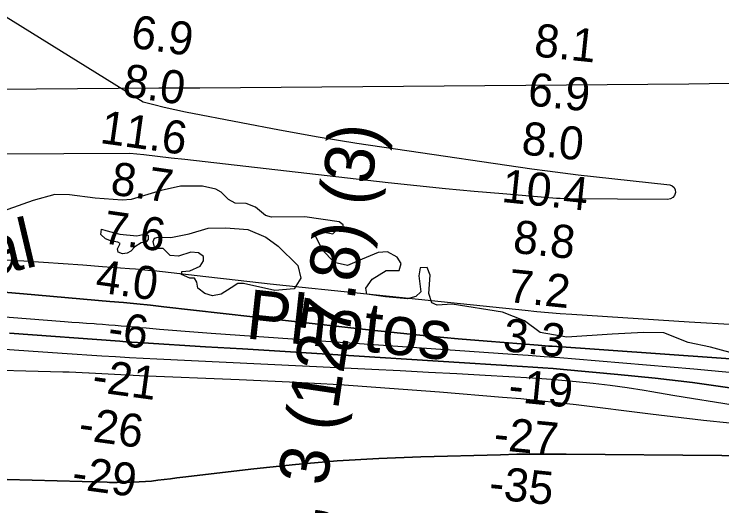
# Model space of a CAD drawing. Extents: x 3535183 to 3573198, y 534952 to 560562.
# Drawn here: x 3563273 to 3564705, y 545747 to 546742 of the extents above; entities that cross this region are included whole.
import ezdxf

# ---------------------------------------------------------------- set-up
doc = ezdxf.new("R2010")
doc.units = 0
for name, color, linetype in [('V-CHAN-NAID', 7, 'Continuous'), ('V-GRID-MAJR', 7, 'Continuous'), ('V-RIVR-EDGE', 7, 'Continuous'), ('V-RIVR-IDEN', 7, 'Continuous'), ('V-RIVR-RANG', 7, 'Continuous'), ('V-TOPO-DPTH', 7, 'Continuous'), ('V-TOPO-MINR', 7, 'Continuous'), ('V-TOPO-WATR', 7, 'Continuous')]:
    doc.layers.add(name, color=color, linetype=linetype)

msp = doc.modelspace()

# ---------------------------------------------------------------- linework, layer by layer
at = {"layer": 'V-GRID-MAJR'}
msp.add_spline([(3539332.196, 546413.546), (3544607.59, 546451.528), (3549882.9790000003, 546490.277), (3555158.363, 546529.794), (3560433.741, 546570.077), (3565709.113, 546611.128), (3570984.478, 546652.946), (3570984.4790000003, 546652.946)], degree=3, dxfattribs=at)
at = {"layer": 'V-RIVR-EDGE'}
for points in [[(3563920.6087827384, 546239.1026320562), (3563896.164998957, 546265.5103381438), (3563882.7532650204, 546293.116219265), (3563893.1907726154, 546301.6685891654), (3563917.6890995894, 546297.3189224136), (3563926.9026756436, 546306.4870458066), (3563938.555024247, 546310.7473223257), (3563938.5671449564, 546315.6491088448), (3563930.61689275, 546321.7960381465), (3563860.7906762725, 546331.7723312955), (3563793.3880814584, 546330.7135444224), (3563781.7554290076, 546334.4186709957), (3563761.5764670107, 546351.0121984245), (3563742.6002253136, 546358.4118459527), (3563720.5437010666, 546359.0791124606), (3563706.4692458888, 546366.4666392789), (3563691.801763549, 546381.82108428), (3563681.400618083, 546387.9740739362), (3563653.841704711, 546393.5567627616), (3563609.72562604, 546393.6658491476), (3563570.4901226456, 546385.1846884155), (3563509.785061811, 546366.9529827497), (3563492.011540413, 546365.1587503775), (3563436.8770476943, 546369.5841715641)], [(3563436.8770476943, 546369.5841715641), (3563385.4234401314, 546375.8386721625), (3563355.401512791, 546376.5256348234), (3563311.8693707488, 546364.9914631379), (3563187.3759363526, 546320.5702241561), (3563091.099591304, 546288.9464807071), (3563021.8209493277, 546272.5741562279), (3562912.122264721, 546264.2672306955), (3562837.9418362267, 546247.9070269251), (3562747.8321166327, 546232.1989387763), (3562660.2020769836, 546228.1265332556), (3562527.250208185, 546232.1316473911), (3562435.984736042, 546244.6118619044), (3562365.595794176, 546274.8095395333), (3562331.952070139, 546297.5636320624), (3562297.674411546, 546311.7411132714), (3562267.640363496, 546307.5262894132), (3562174.503389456, 546306.531136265), (3562088.688793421, 546293.2633357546), (3562023.721940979, 546286.0712553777)], [(3563448.336980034, 546296.0285870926), (3563449.588183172, 546306.4418532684), (3563458.77297254, 546303.9682336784)], [(3563458.77297254, 546303.9682336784), (3563486.94006396, 546296.5458598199), (3563521.24499415, 546293.3973982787), (3563539.635784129, 546297.0282855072), (3563544.529995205, 546293.9525482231), (3563544.5102990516, 546285.9871451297), (3563540.2091151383, 546281.0959642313), (3563529.7882735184, 546279.2835507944), (3563517.51259598, 546270.7357261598), (3563508.9132583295, 546262.1788109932), (3563501.54997293, 546257.9079288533), (3563492.356093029, 546256.7052085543), (3563483.7855420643, 546259.7900363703), (3563482.5782764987, 546267.1457463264), (3563487.5058195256, 546277.5499219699), (3563483.2243317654, 546280.6241441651), (3563470.361687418, 546282.4941309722), (3563458.1193418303, 546287.4262192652), (3563448.336980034, 546296.0285870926)], [(3563564.740774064, 546290.226210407), (3563589.860914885, 546289.5513684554), (3563627.2567332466, 546297.4243511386), (3563665.887088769, 546308.9706435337), (3563701.426556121, 546309.4954917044), (3563746.146267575, 546305.7085503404), (3563782.2590659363, 546290.3010772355), (3563807.3367842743, 546272.4699824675), (3563847.0668340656, 546233.1572095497), (3563853.130433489, 546207.4076794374), (3563839.5974924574, 546185.9956953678), (3563800.374109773, 546182.416321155), (3563737.2984553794, 546196.6650115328), (3563725.6567123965, 546196.693798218), (3563712.1555882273, 546188.1490037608), (3563691.9039019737, 546175.3318120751), (3563674.12583531, 546171.6994097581), (3563658.819873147, 546176.6390734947), (3563644.7529934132, 546187.0902168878), (3563642.945125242, 546199.3492284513), (3563638.063034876, 546207.3267522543), (3563628.872185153, 546207.3494785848), (3563611.7341134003, 546214.7445808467), (3563612.3619876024, 546220.8702989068), (3563628.297339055, 546222.6690765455), (3563649.765381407, 546231.8068981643), (3563655.919886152, 546242.8207669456), (3563655.9410973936, 546251.398893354), (3563646.15570542, 546258.7758145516), (3563630.22792941, 546260.0406534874), (3563605.699300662, 546252.1358539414), (3563588.546078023, 546253.4037230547), (3563574.4882888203, 546267.531206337), (3563557.9447593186, 546267.5721137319), (3563554.303266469, 546281.6738405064), (3563557.3835490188, 546288.4062215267)], [(3563557.3835490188, 546288.4062215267), (3563564.740774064, 546290.226210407)], [(3564743.648330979, 546050.7984651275), (3564681.805698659, 546068.1077419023), (3564636.486899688, 546077.410708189), (3564586.9032789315, 546096.5278531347), (3564546.466570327, 546097.8532956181), (3564482.734255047, 546094.3345249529), (3564390.809091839, 546087.8218317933), (3564336.9136815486, 546097.7587326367), (3564305.72236586, 546121.1194881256), (3564261.035986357, 546138.3863424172), (3564159.363308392, 546154.568653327), (3564128.7225973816, 546152.8062378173), (3564117.7056984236, 546157.735295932), (3564111.6239179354, 546176.1321462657), (3564114.77995492, 546213.5006930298), (3564108.6905989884, 546228.8339267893), (3564094.596447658, 546228.2560505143), (3564091.493438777, 546212.3328197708), (3564095.70220228, 546179.8478784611), (3564085.874387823, 546170.0685468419), (3564068.7075293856, 546165.8219061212), (3564023.9878179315, 546169.608847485), (3563986.6253315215, 546175.2157777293), (3563984.8174633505, 546187.4747892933), (3563997.115867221, 546205.2134636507), (3564025.9578005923, 546222.911230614), (3564051.6921798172, 546222.847596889), (3564056.016090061, 546236.9296275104), (3564048.0825038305, 546249.8165132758), (3564028.502629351, 546260.8940157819), (3564009.5051764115, 546259.7155369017), (3563976.995993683, 546245.7032003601), (3563947.5534577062, 546232.9087350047), (3563920.6087827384, 546239.1026320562)]]:
    msp.add_lwpolyline(points, dxfattribs=at)
at = {"layer": 'V-TOPO-DPTH'}
for points in [[(3562632.7349828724, 547124.667376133), (3563534.0579824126, 546564.236942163), (3563555.4448023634, 546558.7873249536), (3563576.896173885, 546553.6175180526), (3563598.4443727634, 546548.8674266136), (3563620.0571232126, 546544.3971454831), (3563732.2801317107, 546522.3255797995), (3563810.1535174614, 546507.6194501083), (3563888.161065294, 546493.6994274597), (3563966.3698562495, 546480.9585653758), (3564044.712809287, 546469.0038103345), (3564320.5354716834, 546429.0427956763), (3564351.62725476, 546424.7017036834), (3564382.746292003, 546420.5745643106), (3564413.9062104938, 546416.768353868), (3564445.0933831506, 546413.1760960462), (3564599.0478739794, 546396.246450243), (3564604.374294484, 546394.1276473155), (3564608.362350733, 546390.9867049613), (3564610.342860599, 546386.3125534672), (3564610.9850062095, 546380.616262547), (3564608.6808124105, 546374.985924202), (3564605.340105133, 546370.5786452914), (3564600.4446276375, 546368.0059555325), (3564594.5126366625, 546366.6563252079), (3564392.151822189, 546368.2597698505), (3564384.79629077, 546368.3997592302), (3564377.4456505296, 546368.6485274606), (3564370.102347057, 546369.0604639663), (3564362.7639347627, 546369.5811793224), (3564261.4945348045, 546377.8983039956), (3564203.5519701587, 546382.93338135), (3564145.645231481, 546388.3338792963), (3564087.792231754, 546394.2825081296), (3564029.975057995, 546400.5965575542), (3563618.427723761, 546447.5135071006), (3563590.6980362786, 546450.6660744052), (3563562.967061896, 546453.8072492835), (3563535.234157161, 546456.9313355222), (3563507.4999655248, 546460.0440293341), (3562438.845673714, 546454.3916878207)], [(3563212.017228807, 546182.3422016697), (3563292.346897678, 546175.9260687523), (3563466.9244357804, 546160.5519434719), (3563494.239026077, 546158.0473020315), (3563521.5404849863, 546155.4115806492), (3563548.8222468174, 546152.5792393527), (3563576.090877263, 546149.6158181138), (3563996.1826714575, 546102.4305413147), (3564054.592260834, 546096.1519105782), (3564113.0376461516, 546090.2451974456), (3564171.5367253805, 546084.8963607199), (3564230.07160055, 546079.9194415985), (3564333.1316902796, 546071.6517846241), (3564340.164161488, 546071.0981699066), (3564347.197683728, 546070.5585268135), (3564354.2327825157, 546070.0398411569), (3564361.2689323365, 546069.5351271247), (3565026.056004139, 546022.8442086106)], [(3563212.017228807, 546182.3422016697), (3563292.346897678, 546175.9260687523), (3563466.9244357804, 546160.5519434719), (3563494.239026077, 546158.0473020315), (3563521.5404849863, 546155.4115806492), (3563548.8222468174, 546152.5792393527), (3563576.090877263, 546149.6158181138), (3563996.1826714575, 546102.4305413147), (3564054.592260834, 546096.1519105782), (3564113.0376461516, 546090.2451974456), (3564171.5367253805, 546084.8963607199), (3564230.07160055, 546079.9194415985), (3564333.1316902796, 546071.6517846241), (3564340.164161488, 546071.0981699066), (3564347.197683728, 546070.5585268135), (3564354.2327825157, 546070.0398411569), (3564361.2689323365, 546069.5351271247), (3565026.056004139, 546022.8442086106)], [(3563264.096077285, 546096.1309951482), (3563487.180566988, 546079.7043587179), (3563498.9790974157, 546078.8574095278), (3563510.7795814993, 546078.0394163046), (3563522.582996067, 546077.2648570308), (3563534.38836429, 546076.5192537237), (3563660.5084267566, 546068.7867398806), (3563735.374514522, 546064.184039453), (3563810.239566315, 546059.5645952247), (3563885.103064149, 546054.920035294), (3563959.965526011, 546050.258731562), (3564301.2877432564, 546028.9488612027), (3564321.9931521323, 546027.5684165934), (3564342.689647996, 546026.0715641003), (3564363.3727743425, 546024.400099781), (3564384.046987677, 546022.6122275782), (3564494.088390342, 546012.6280233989), (3564569.673329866, 546004.9479271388), (3564645.12069832, 545996.1852597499), (3564720.3617101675, 545985.7987356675)], [(3564720.3617101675, 545985.7987356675), (3564645.12069832, 545996.1852597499), (3564569.673329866, 546004.9479271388), (3564494.088390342, 546012.6280233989), (3564384.046987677, 546022.6122275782), (3564363.3727743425, 546024.400099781), (3564342.689647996, 546026.0715641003), (3564321.9931521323, 546027.5684165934), (3564301.2877432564, 546028.9488612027), (3563959.965526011, 546050.258731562), (3563885.103064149, 546054.920035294), (3563810.239566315, 546059.5645952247), (3563735.374514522, 546064.184039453), (3563660.5084267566, 546068.7867398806), (3563534.38836429, 546076.5192537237), (3563522.582996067, 546077.2648570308), (3563510.7795814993, 546078.0394163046), (3563498.9790974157, 546078.8574095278), (3563487.180566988, 546079.7043587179), (3563264.096077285, 546096.1309951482)], [(3564774.2205996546, 545908.4605705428), (3564667.1605373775, 545919.6061873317), (3564560.2197932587, 545932.0044734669), (3564409.585964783, 545950.8084083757), (3564372.4258403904, 545955.2109349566), (3564335.233486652, 545959.3026002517), (3564297.992788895, 545962.9279736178), (3564260.719861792, 545966.242485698), (3564133.248589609, 545976.7734592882), (3564032.176565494, 545984.4810185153), (3563931.0521872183, 545991.3366138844), (3563829.849277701, 545996.9142634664), (3563728.594014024, 546001.6399491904), (3563526.957399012, 546009.7744775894), (3563514.2028516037, 546010.327857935), (3563501.4509128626, 546010.9329016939), (3563488.702887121, 546011.6154405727), (3563475.9574700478, 546012.349642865), (3563463.2134537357, 546013.1130354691), (3563450.468696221, 546013.8636807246), (3563437.7228269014, 546014.5952049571), (3563424.9762163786, 546015.3139818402), (3563424.126910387, 546015.3612348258), (3563410.9526769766, 546016.0345444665), (3563397.775225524, 546016.6284915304), (3563384.592947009, 546017.1033947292), (3563371.4074504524, 546017.4989353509), (3563172.423811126, 546022.5687289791)], [(3564774.2205996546, 545908.4605705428), (3564667.1605373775, 545919.6061873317), (3564560.2197932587, 545932.0044734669), (3564409.585964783, 545950.8084083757), (3564372.4258403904, 545955.2109349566), (3564335.233486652, 545959.3026002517), (3564297.992788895, 545962.9279736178), (3564260.719861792, 545966.242485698), (3564133.248589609, 545976.7734592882), (3564032.176565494, 545984.4810185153), (3563931.0521872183, 545991.3366138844), (3563829.849277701, 545996.9142634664), (3563728.594014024, 546001.6399491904), (3563526.957399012, 546009.7744775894), (3563514.2028516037, 546010.327857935), (3563501.4509128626, 546010.9329016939), (3563488.702887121, 546011.6154405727), (3563475.9574700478, 546012.349642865), (3563463.2134537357, 546013.1130354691), (3563450.468696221, 546013.8636807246), (3563437.7228269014, 546014.5952049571), (3563424.9762163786, 546015.3139818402), (3563424.126910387, 546015.3612348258), (3563410.9526769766, 546016.0345444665), (3563397.775225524, 546016.6284915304), (3563384.592947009, 546017.1033947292), (3563371.4074504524, 546017.4989353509), (3563172.423811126, 546022.5687289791)], [(3563157.082682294, 545802.445168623), (3563461.048240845, 545794.3245943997), (3563466.1958055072, 545794.2180888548), (3563471.343644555, 545794.1529139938), (3563476.491895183, 545794.1497351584), (3563481.6404201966, 545794.187887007), (3563513.192111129, 545794.6117047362), (3563525.933087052, 545795.0125819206), (3563538.651609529, 545795.718551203), (3563551.3364518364, 545796.882158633), (3563563.9988406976, 545798.3508581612), (3563576.648256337, 545800.01796516), (3563589.3028950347, 545801.6436080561), (3563601.965368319, 545803.2070547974), (3563614.6330646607, 545804.7290374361), (3563757.660172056, 545821.5569379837), (3563841.9279727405, 545830.3154208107), (3563926.3057638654, 545837.5480318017), (3564010.8485406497, 545842.4918350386), (3564095.5013078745, 545845.9097664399), (3564257.166889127, 545850.243686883), (3564290.211841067, 545850.9553696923), (3564323.2589384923, 545851.434924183), (3564356.3092541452, 545851.5662861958), (3564389.3617152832, 545851.4655198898), (3564704.264103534, 545848.8465093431), (3564787.5531320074, 545847.8419242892)], [(3564787.5531320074, 545847.8419242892), (3564704.264103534, 545848.8465093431), (3564389.3617152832, 545851.4655198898), (3564356.3092541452, 545851.5662861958), (3564323.2589384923, 545851.434924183), (3564290.211841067, 545850.9553696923), (3564257.166889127, 545850.243686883), (3564095.5013078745, 545845.9097664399), (3564010.8485406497, 545842.4918350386), (3563926.3057638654, 545837.5480318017), (3563841.9279727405, 545830.3154208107), (3563757.660172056, 545821.5569379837), (3563614.6330646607, 545804.7290374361), (3563601.965368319, 545803.2070547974), (3563589.3028950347, 545801.6436080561), (3563576.648256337, 545800.01796516), (3563563.9988406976, 545798.3508581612), (3563551.3364518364, 545796.882158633), (3563538.651609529, 545795.718551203), (3563525.933087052, 545795.0125819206), (3563513.192111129, 545794.6117047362), (3563481.6404201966, 545794.187887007), (3563476.491895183, 545794.1497351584), (3563471.343644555, 545794.1529139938), (3563466.1958055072, 545794.2180888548), (3563461.048240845, 545794.3245943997), (3563157.082682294, 545802.445168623)]]:
    msp.add_lwpolyline(points, dxfattribs=at)
at = {"layer": 'V-TOPO-MINR'}
for points in [[(3562632.7349828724, 547124.667376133), (3563534.0579824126, 546564.236942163), (3563555.4448023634, 546558.7873249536), (3563576.896173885, 546553.6175180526), (3563598.4443727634, 546548.8674266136), (3563620.0571232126, 546544.3971454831), (3563732.2801317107, 546522.3255797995), (3563810.1535174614, 546507.6194501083), (3563888.161065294, 546493.6994274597), (3563966.3698562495, 546480.9585653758), (3564044.712809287, 546469.0038103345), (3564320.5354716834, 546429.0427956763), (3564351.62725476, 546424.7017036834), (3564382.746292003, 546420.5745643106), (3564413.9062104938, 546416.768353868), (3564445.0933831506, 546413.1760960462), (3564599.0478739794, 546396.246450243), (3564604.374294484, 546394.1276473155), (3564608.362350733, 546390.9867049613), (3564610.342860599, 546386.3125534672), (3564610.9850062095, 546380.616262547), (3564608.6808124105, 546374.985924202), (3564605.340105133, 546370.5786452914), (3564600.4446276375, 546368.0059555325), (3564594.5126366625, 546366.6563252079), (3564392.151822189, 546368.2597698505), (3564384.79629077, 546368.3997592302), (3564377.4456505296, 546368.6485274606), (3564370.102347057, 546369.0604639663), (3564362.7639347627, 546369.5811793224), (3564261.4945348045, 546377.8983039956), (3564203.5519701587, 546382.93338135), (3564145.645231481, 546388.3338792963), (3564087.792231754, 546394.2825081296), (3564029.975057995, 546400.5965575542), (3563618.427723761, 546447.5135071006), (3563590.6980362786, 546450.6660744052), (3563562.967061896, 546453.8072492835), (3563535.234157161, 546456.9313355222), (3563507.4999655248, 546460.0440293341), (3562438.845673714, 546454.3916878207)], [(3564732.2122414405, 546112.9656447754), (3564638.1394924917, 546118.6629606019), (3564401.2557839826, 546133.8296563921), (3564377.604550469, 546135.4844330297), (3564353.9689330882, 546137.3254622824), (3564330.356739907, 546139.4458704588), (3564306.7601628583, 546141.7525312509), (3563921.0445141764, 546181.7617987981), (3563856.0281464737, 546188.6031375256), (3563791.0257348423, 546195.5728423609), (3563726.04425732, 546202.7350963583), (3563661.0767358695, 546210.0257164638), (3563555.588538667, 546222.0218024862), (3563543.3687644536, 546223.3378736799), (3563531.1399017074, 546224.5569333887), (3563518.8974061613, 546225.6304758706), (3563506.6458220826, 546226.6070068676), (3563451.7953549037, 546230.650847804), (3563412.108101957, 546233.524344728), (3563372.4160268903, 546236.3282799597), (3563332.7167186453, 546239.0278726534), (3563293.012588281, 546241.6579036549), (3563279.9821425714, 546242.5038506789), (3563233.756989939, 546245.4696960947)], [(3564740.629555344, 546014.6490810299), (3564647.824797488, 546023.0807489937), (3564408.71715883, 546043.3141037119), (3564376.8432674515, 546045.9397671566), (3564344.962068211, 546048.4707012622), (3564313.069907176, 546050.8595413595), (3564281.1704382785, 546053.1536521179), (3563671.379125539, 546095.6424499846), (3563645.297474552, 546097.5297130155), (3563619.2231165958, 546099.5097364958), (3563593.1596981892, 546101.6289006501), (3563567.1035728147, 546103.840825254), (3563540.1297293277, 546106.2031770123), (3563527.566080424, 546107.3044637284), (3563515.0025443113, 546108.4070345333), (3563502.4391773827, 546109.5115314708), (3563489.875923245, 546110.6173124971), (3563477.3096364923, 546111.6837495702), (3563464.739193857, 546112.6964490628), (3563452.162517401, 546113.6285421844), (3563439.5816850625, 546114.5068977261), (3563434.8056404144, 546114.8249661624), (3563419.835678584, 546115.8496676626), (3563404.8683967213, 546116.9111930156), (3563389.9051348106, 546118.0279541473), (3563374.9445528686, 546119.1815391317), (3563013.157055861, 546147.7500915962)], [(3564720.3617101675, 545985.7987356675), (3564645.12069832, 545996.1852597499), (3564569.673329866, 546004.9479271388), (3564494.088390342, 546012.6280233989), (3564384.046987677, 546022.6122275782), (3564363.3727743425, 546024.400099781), (3564342.689647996, 546026.0715641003), (3564321.9931521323, 546027.5684165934), (3564301.2877432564, 546028.9488612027), (3563959.965526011, 546050.258731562), (3563885.103064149, 546054.920035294), (3563810.239566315, 546059.5645952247), (3563735.374514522, 546064.184039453), (3563660.5084267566, 546068.7867398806), (3563534.38836429, 546076.5192537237), (3563522.582996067, 546077.2648570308), (3563510.7795814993, 546078.0394163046), (3563498.9790974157, 546078.8574095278), (3563487.180566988, 546079.7043587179), (3563264.096077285, 546096.1309951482)], [(3564731.583757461, 545949.4625793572), (3564689.4756805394, 545956.3852988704), (3564647.371850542, 545963.333679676), (3564605.274390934, 545970.3205524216), (3564563.1811782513, 545977.3330864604), (3564547.6160230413, 545979.9334826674), (3564513.2585633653, 545985.276560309), (3564478.834502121, 545990.1022394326), (3564444.3105385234, 545994.1518207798), (3564409.7199733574, 545997.6840036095), (3564359.359577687, 546002.2542769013), (3564349.8957125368, 546003.0657284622), (3564340.4271977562, 546003.8144072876), (3564330.9517085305, 546004.4689270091), (3564321.471569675, 546005.0606739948), (3564225.8581936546, 546010.5518708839), (3564168.563586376, 546013.7606410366), (3564111.2632560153, 546016.8607666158), (3564053.9543410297, 546019.7979253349), (3563996.6397029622, 546022.6264394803), (3563562.094190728, 546043.4521805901), (3563534.226889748, 546044.8630918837), (3563506.3652945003, 546046.3742048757), (3563478.5122578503, 546048.0356204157), (3563450.6649269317, 546049.7972376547), (3563370.151113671, 546055.1086398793), (3563302.05332776, 546059.6332693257), (3563233.9584379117, 546064.2007716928)], [(3564774.2205996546, 545908.4605705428), (3564667.1605373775, 545919.6061873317), (3564560.2197932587, 545932.0044734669), (3564409.585964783, 545950.8084083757), (3564372.4258403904, 545955.2109349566), (3564335.233486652, 545959.3026002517), (3564297.992788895, 545962.9279736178), (3564260.719861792, 545966.242485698), (3564133.248589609, 545976.7734592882), (3564032.176565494, 545984.4810185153), (3563931.0521872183, 545991.3366138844), (3563829.849277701, 545996.9142634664), (3563728.594014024, 546001.6399491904), (3563526.957399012, 546009.7744775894), (3563514.2028516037, 546010.327857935), (3563501.4509128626, 546010.9329016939), (3563488.702887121, 546011.6154405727), (3563475.9574700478, 546012.349642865), (3563463.2134537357, 546013.1130354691), (3563450.468696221, 546013.8636807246), (3563437.7228269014, 546014.5952049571), (3563424.9762163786, 546015.3139818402), (3563424.126910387, 546015.3612348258), (3563410.9526769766, 546016.0345444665), (3563397.775225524, 546016.6284915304), (3563384.592947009, 546017.1033947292), (3563371.4074504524, 546017.4989353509), (3563172.423811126, 546022.5687289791)], [(3564787.5531320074, 545847.8419242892), (3564704.264103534, 545848.8465093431), (3564389.3617152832, 545851.4655198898), (3564356.3092541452, 545851.5662861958), (3564323.2589384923, 545851.434924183), (3564290.211841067, 545850.9553696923), (3564257.166889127, 545850.243686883), (3564095.5013078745, 545845.9097664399), (3564010.8485406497, 545842.4918350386), (3563926.3057638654, 545837.5480318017), (3563841.9279727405, 545830.3154208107), (3563757.660172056, 545821.5569379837), (3563614.6330646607, 545804.7290374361), (3563601.965368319, 545803.2070547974), (3563589.3028950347, 545801.6436080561), (3563576.648256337, 545800.01796516), (3563563.9988406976, 545798.3508581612), (3563551.3364518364, 545796.882158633), (3563538.651609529, 545795.718551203), (3563525.933087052, 545795.0125819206), (3563513.192111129, 545794.6117047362), (3563481.6404201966, 545794.187887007), (3563476.491895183, 545794.1497351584), (3563471.343644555, 545794.1529139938), (3563466.1958055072, 545794.2180888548), (3563461.048240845, 545794.3245943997), (3563157.082682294, 545802.445168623)]]:
    msp.add_lwpolyline(points, dxfattribs=at)
at = {"layer": 'V-TOPO-WATR'}
msp.add_lwpolyline([(3565026.056004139, 546022.8442086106), (3564361.2689323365, 546069.5351271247), (3564354.2327825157, 546070.0398411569), (3564347.197683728, 546070.5585268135), (3564340.164161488, 546071.0981699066), (3564333.1316902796, 546071.6517846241), (3564230.07160055, 546079.9194415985), (3564171.5367253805, 546084.8963607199), (3564113.0376461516, 546090.2451974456), (3564054.592260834, 546096.1519105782), (3563996.1826714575, 546102.4305413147), (3563576.090877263, 546149.6158181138), (3563548.8222468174, 546152.5792393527), (3563521.5404849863, 546155.4115806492), (3563494.239026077, 546158.0473020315), (3563466.9244357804, 546160.5519434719), (3563292.346897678, 546175.9260687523), (3563212.017228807, 546182.3422016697)], dxfattribs=at)

# ---------------------------------------------------------------- texts
at = {"layer": 'V-CHAN-NAID'}
msp.add_text('UNION CARBIDE TAFT NO. 2, 3 (127.8) (3)', height=100.00000199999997, rotation=81.53340734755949, dxfattribs=at).set_placement((3563626.145622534, 543911.0223182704))
at = {"layer": 'V-RIVR-IDEN'}
for s, rotation, p in [('Aerial', 13.294949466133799, (3562991.3140896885, 546154.4544961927)), ('Photos', 353.7788381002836, (3563739.5819502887, 546085.9466678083))]:
    msp.add_text(s, height=99.99980199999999, rotation=rotation, dxfattribs=at).set_placement(p)
at = {"layer": 'V-RIVR-RANG'}
for s, height, rotation, p in [('6.9', 67, 351.9483257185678, (3563506.9875347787, 546674.5318777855)), ('8.1', 67, 354.0583257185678, (3564323.1060425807, 546656.7681714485)), ('8.0', 67, 351.9483257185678, (3563490.6187424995, 546575.8523436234)), ('6.9', 67, 354.0583257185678, (3564310.3814181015, 546557.5522254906)), ('11.6', 67, 351.9483257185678, (3563444.9988766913, 546481.3108268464)), ('8.0', 67, 354.0583257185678, (3564297.657793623, 546458.3372795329)), ('8.7', 67, 351.9483257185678, (3563465.979714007, 546377.3469312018)), ('10.4', 67, 354.0583257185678, (3564257.386112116, 546361.9884010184)), ('7.6', 67, 351.9483257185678, (3563450.3954594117, 546278.5565572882)), ('8.8', 67, 354.0583257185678, (3564280.3427805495, 546259.0599200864)), ('4.0', 67, 351.9483257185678, (3563435.5937424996, 546179.6553436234)), ('7.2', 67, 354.0583257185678, (3564270.2427805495, 546159.5709200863)), ('-6', 67.00000000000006, 352.2348333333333, (3563460.6242538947, 546074.8698881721)), ('3.3', 67, 354.0583257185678, (3564260.1417805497, 546060.0819200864)), ('-21', 67.00000000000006, 352.2348333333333, (3563428.8343646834, 545978.2800550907)), ('-19', 67.00000000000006, 354.3446666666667, (3564271.1648419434, 545958.072563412)), ('-26', 67.00000000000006, 352.2348333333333, (3563401.226246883, 545881.1199804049)), ('-27', 67.00000000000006, 354.3446666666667, (3564241.3776695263, 545860.5331050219)), ('-29', 67.00000000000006, 352.2348333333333, (3563387.7316075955, 545782.0343403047)), ('-35', 67.00000000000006, 354.3446666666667, (3564231.8016607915, 545760.9931172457))]:
    msp.add_text(s, height=height, rotation=rotation, dxfattribs=at).set_placement(p)

doc.saveas('drawing.dxf')
